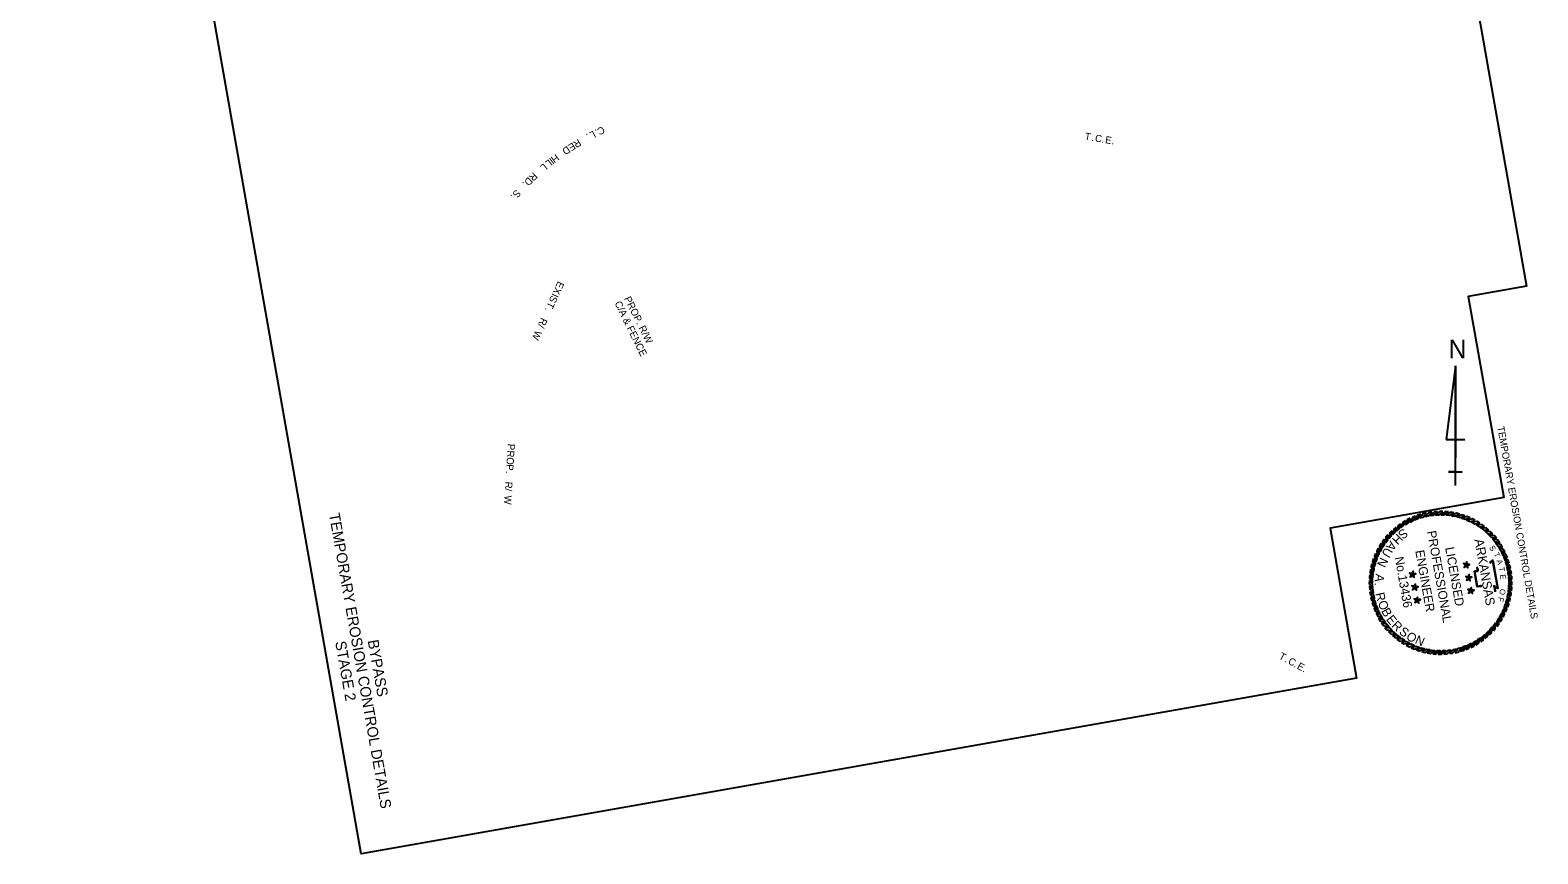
# Model space of a CAD drawing. Extents: x 979945 to 981206, y 1838799 to 1840551.
# Drawn here: x 979945 to 981206, y 1838799 to 1839488 of the extents above; entities that cross this region are included whole.
import ezdxf

# ---------------------------------------------------------------- set-up
doc = ezdxf.new("R2010")
doc.units = 0
for name, color, linetype in [('1', 7, 'Continuous'), ('60', 7, 'Continuous'), ('63', 7, 'Continuous'), ('Default', 7, 'Continuous'), ('G-ANNO-SYMB', 7, 'Continuous'), ('R_Draft', 7, 'Continuous')]:
    doc.layers.add(name, color=color, linetype=linetype)

msp = doc.modelspace()

# ---------------------------------------------------------------- linework, layer by layer
at = {"layer": '63'}
for p, q in [((981136.7, 1839206.9), (981129, 1839145.3)), ((981136.7, 1839106.9), (981136.7, 1839206.9)), ((981136.7, 1839206.9), (981136.7, 1839129.9)), ((981129, 1839145.3), (981144.4, 1839145.3)), ((981136.7, 1839106.9), (981136.7, 1839129.9)), ((981136.7, 1839118.4), (981130.9, 1839118.4)), ((981130.9, 1839118.4), (981142.4, 1839118.4)), ((981136.7, 1839106.9), (981136.7, 1839118.4))]:
    msp.add_line(p, q, dxfattribs=at)
at = {"layer": 'Default'}
msp.add_lwpolyline([(979944.5, 1840369.9), (980971, 1840550.9), (981196.2, 1839273.6), (981147.4, 1839265), (981177.1, 1839096.8), (981031.8, 1839071.2), (981054, 1838945.6), (980221.5, 1838798.8)], close=True, dxfattribs=at)
msp.add_lwpolyline([(979944.5, 1840369.9), (980971, 1840550.9), (981196.2, 1839273.6), (981147.4, 1839265), (981177.1, 1839096.8), (981031.8, 1839071.2), (981054, 1838945.6), (980221.5, 1838798.8)], close=True, dxfattribs=at)
at = {"layer": 'G-ANNO-SYMB'}
for points in [[(981094.8, 1839077.3), (981092.6, 1839076), (981091, 1839071.7), (981093.3, 1839073.3)], [(981098.9, 1839079.5), (981096.6, 1839078.3), (981094.8, 1839074.2), (981097.2, 1839075.5)], [(981103.3, 1839081.3), (981100.9, 1839080.3), (981098.7, 1839076.3), (981101.2, 1839077.5)], [(981107.7, 1839082.8), (981105.2, 1839082), (981102.8, 1839078.2), (981105.3, 1839079.2)], [(981112.2, 1839083.9), (981109.7, 1839083.3), (981107, 1839079.7), (981109.6, 1839080.5)], [(981116.9, 1839084.7), (981114.3, 1839084.3), (981111.3, 1839080.9), (981114, 1839081.5)], [(981121.5, 1839085.1), (981119, 1839084.9), (981115.7, 1839081.7), (981118.4, 1839082.1)], [(981126.2, 1839085.1), (981123.7, 1839085.1), (981120.1, 1839082.2), (981122.9, 1839082.4)], [(981130.9, 1839084.8), (981128.3, 1839085), (981124.6, 1839082.4), (981127.3, 1839082.3)], [(981135.5, 1839084.1), (981133, 1839084.5), (981129, 1839082.2), (981131.8, 1839081.9)], [(981140.1, 1839083), (981137.6, 1839083.6), (981133.5, 1839081.6), (981136.2, 1839081.1)], [(981144.5, 1839081.6), (981142.1, 1839082.4), (981137.8, 1839080.8), (981140.5, 1839080)], [(981148.9, 1839079.8), (981146.5, 1839080.8), (981142.1, 1839079.5), (981144.8, 1839078.6)], [(981153.1, 1839077.7), (981150.8, 1839078.9), (981146.3, 1839077.9), (981148.9, 1839076.8)], [(981080.2, 1839065.7), (981078.5, 1839063.7), (981078.4, 1839059.2), (981080.1, 1839061.3)], [(981083.5, 1839069), (981081.7, 1839067.2), (981081.2, 1839062.7), (981083, 1839064.7)], [(981087, 1839072.1), (981085.1, 1839070.4), (981084.2, 1839065.9), (981086.2, 1839067.8)], [(981090.8, 1839074.8), (981088.7, 1839073.4), (981087.5, 1839068.9), (981089.7, 1839070.7)], [(981157.1, 1839075.3), (981154.9, 1839076.7), (981150.4, 1839076.1), (981152.8, 1839074.7)], [(981160.9, 1839072.6), (981158.8, 1839074.1), (981154.3, 1839073.9), (981156.6, 1839072.3)], [(981164.5, 1839069.5), (981162.5, 1839071.2), (981158, 1839071.4), (981160.2, 1839069.7)], [(981167.8, 1839066.3), (981166, 1839068.1), (981161.5, 1839068.6), (981163.5, 1839066.7)], [(981170.9, 1839062.7), (981169.2, 1839064.7), (981164.7, 1839065.5), (981166.6, 1839063.5)], [(981072, 1839054.3), (981070.8, 1839052), (981071.8, 1839047.5), (981072.9, 1839050)], [(981074.5, 1839058.3), (981073.1, 1839056.1), (981073.7, 1839051.6), (981075, 1839054)], [(981077.2, 1839062.1), (981075.6, 1839060), (981075.9, 1839055.5), (981077.4, 1839057.8)], [(981173.7, 1839058.9), (981172.2, 1839061), (981167.8, 1839062.2), (981169.5, 1839060.1)], [(981176.1, 1839055), (981174.8, 1839057.2), (981170.5, 1839058.7), (981172.1, 1839056.4)], [(981178.3, 1839050.8), (981177.1, 1839053.1), (981173, 1839055), (981174.3, 1839052.6)], [(981066.8, 1839041.3), (981066.1, 1839038.8), (981068.1, 1839034.7), (981068.6, 1839037.4)], [(981068.2, 1839045.7), (981067.3, 1839043.3), (981069, 1839039), (981069.7, 1839041.7)], [(981069.9, 1839050.1), (981068.9, 1839047.7), (981070.2, 1839043.3), (981071.2, 1839045.9)], [(981145.8, 1839040.3), (981145.3, 1839041.2), (981143.3, 1839041.5), (981144.8, 1839040.1)], [(981145.8, 1839040.3), (981144.8, 1839040.1), (981143.9, 1839038.4), (981145.6, 1839039.3)], [(981145.8, 1839040.3), (981146.5, 1839041.1), (981146.2, 1839043), (981145.3, 1839041.2)], [(981145.8, 1839040.3), (981145.6, 1839039.3), (981147.1, 1839037.9), (981146.7, 1839039.9)], [(981145.8, 1839040.3), (981146.7, 1839039.9), (981148.5, 1839040.8), (981146.5, 1839041.1)], [(981180.1, 1839046.5), (981179.2, 1839048.9), (981175.1, 1839051.1), (981176.3, 1839048.5)], [(981181.6, 1839042), (981180.8, 1839044.5), (981177, 1839047), (981178, 1839044.4)], [(981182.7, 1839037.5), (981182.1, 1839040), (981178.5, 1839042.8), (981179.3, 1839040.1)], [(981064.7, 1839027.4), (981064.6, 1839024.8), (981067.5, 1839021.3), (981067.4, 1839024)], [(981065, 1839032.1), (981064.8, 1839029.5), (981067.3, 1839025.7), (981067.4, 1839028.5)], [(981065.7, 1839036.7), (981065.3, 1839034.2), (981067.5, 1839030.2), (981067.8, 1839033)], [(981100.8, 1839032.4), (981100.3, 1839033.3), (981098.3, 1839033.6), (981099.8, 1839032.2)], [(981100.8, 1839032.4), (981099.8, 1839032.2), (981098.9, 1839030.4), (981100.6, 1839031.4)], [(981100.8, 1839032.4), (981101.5, 1839033.1), (981101.2, 1839035.1), (981100.3, 1839033.3)], [(981100.8, 1839032.4), (981100.6, 1839031.4), (981102.1, 1839030), (981101.7, 1839031.9)], [(981100.8, 1839032.4), (981101.7, 1839031.9), (981103.5, 1839032.9), (981101.5, 1839033.1)], [(981147.7, 1839029.6), (981147.2, 1839030.5), (981145.2, 1839030.8), (981146.6, 1839029.4)], [(981147.7, 1839029.6), (981146.6, 1839029.4), (981145.8, 1839027.6), (981147.5, 1839028.6)], [(981147.7, 1839029.6), (981148.4, 1839030.3), (981148.1, 1839032.3), (981147.2, 1839030.5)], [(981147.7, 1839029.6), (981147.5, 1839028.6), (981149, 1839027.2), (981148.6, 1839029.1)], [(981147.7, 1839029.6), (981148.6, 1839029.1), (981150.4, 1839030.1), (981148.4, 1839030.3)], [(981183.5, 1839032.9), (981183.1, 1839035.4), (981179.7, 1839038.5), (981180.3, 1839035.8)], [(981183.9, 1839028.2), (981183.7, 1839030.8), (981180.6, 1839034.1), (981180.9, 1839031.3)], [(981183.9, 1839023.5), (981183.9, 1839026.1), (981181.1, 1839029.6), (981181.2, 1839026.9)], [(981064.7, 1839022.7), (981064.9, 1839020.2), (981068, 1839016.8), (981067.7, 1839019.6)], [(981065.1, 1839018), (981065.5, 1839015.5), (981068.9, 1839012.4), (981068.3, 1839015.2)], [(981102.7, 1839021.7), (981102.2, 1839022.6), (981100.2, 1839022.8), (981101.7, 1839021.5)], [(981102.7, 1839021.7), (981101.7, 1839021.5), (981100.8, 1839019.7), (981102.5, 1839020.6)], [(981102.7, 1839021.7), (981103.4, 1839022.4), (981103.1, 1839024.4), (981102.2, 1839022.6)], [(981102.7, 1839021.7), (981102.5, 1839020.6), (981104, 1839019.2), (981103.6, 1839021.2)], [(981102.7, 1839021.7), (981103.6, 1839021.2), (981105.4, 1839022.1), (981103.4, 1839022.4)], [(981149.6, 1839018.8), (981149.1, 1839019.8), (981147.1, 1839020), (981148.5, 1839018.7)], [(981149.6, 1839018.8), (981148.5, 1839018.7), (981147.7, 1839016.9), (981149.4, 1839017.8)], [(981149.6, 1839018.8), (981150.3, 1839019.6), (981149.9, 1839021.5), (981149.1, 1839019.8)], [(981149.6, 1839018.8), (981149.4, 1839017.8), (981150.8, 1839016.4), (981150.5, 1839018.4)], [(981149.6, 1839018.8), (981150.5, 1839018.4), (981152.3, 1839019.3), (981150.3, 1839019.6)], [(981181.8, 1839009.7), (981182.4, 1839012.1), (981180.5, 1839016.3), (981180, 1839013.5)], [(981182.9, 1839014.2), (981183.3, 1839016.7), (981181, 1839020.7), (981180.7, 1839018)], [(981183.6, 1839018.8), (981183.8, 1839021.4), (981181.2, 1839025.2), (981181.1, 1839022.4)], [(981065.8, 1839013.4), (981066.4, 1839010.9), (981070, 1839008.1), (981069.3, 1839010.8)], [(981067, 1839008.9), (981067.7, 1839006.4), (981071.6, 1839003.9), (981070.6, 1839006.5)], [(981068.4, 1839004.4), (981069.4, 1839002.1), (981073.4, 1838999.9), (981072.2, 1839002.4)], [(981104.6, 1839010.9), (981104.1, 1839011.8), (981102.1, 1839012.1), (981103.6, 1839010.7)], [(981104.6, 1839010.9), (981103.6, 1839010.7), (981102.7, 1839008.9), (981104.4, 1839009.9)], [(981104.6, 1839010.9), (981105.3, 1839011.7), (981105, 1839013.6), (981104.1, 1839011.8)], [(981104.6, 1839010.9), (981104.4, 1839009.9), (981105.9, 1839008.5), (981105.5, 1839010.5)], [(981104.6, 1839010.9), (981105.5, 1839010.5), (981107.3, 1839011.4), (981105.3, 1839011.7)], [(981176.5, 1838996.7), (981177.7, 1838998.9), (981176.8, 1839003.4), (981175.6, 1839000.9)], [(981178.6, 1839000.9), (981179.6, 1839003.2), (981178.3, 1839007.6), (981177.4, 1839005)], [(981180.4, 1839005.2), (981181.2, 1839007.6), (981179.6, 1839011.9), (981178.8, 1839009.2)], [(981070.3, 1839000.1), (981071.4, 1838997.8), (981075.6, 1838996), (981074.2, 1838998.4)], [(981072.4, 1838996), (981073.7, 1838993.8), (981078.1, 1838992.2), (981076.5, 1838994.5)], [(981074.9, 1838992), (981076.4, 1838989.9), (981080.8, 1838988.7), (981079.1, 1838990.9)], [(981168.4, 1838985.3), (981170, 1838987.2), (981170.2, 1838991.8), (981168.5, 1838989.6)], [(981171.4, 1838988.8), (981172.9, 1838990.9), (981172.7, 1838995.5), (981171.2, 1838993.1)], [(981174.1, 1838992.7), (981175.5, 1838994.8), (981174.9, 1838999.4), (981173.5, 1838996.9)], [(981077.7, 1838988.2), (981079.3, 1838986.2), (981083.8, 1838985.4), (981081.9, 1838987.4)], [(981080.7, 1838984.7), (981082.5, 1838982.8), (981087.1, 1838982.4), (981085, 1838984.2)], [(981084.1, 1838981.4), (981086, 1838979.7), (981090.6, 1838979.6), (981088.4, 1838981.3)], [(981087.7, 1838978.4), (981089.7, 1838976.8), (981094.3, 1838977.1), (981092, 1838978.6)], [(981091.5, 1838975.6), (981093.6, 1838974.3), (981098.2, 1838974.9), (981095.7, 1838976.2)], [(981149.6, 1838971.5), (981151.9, 1838972.6), (981153.8, 1838976.8), (981151.4, 1838975.4)], [(981153.8, 1838973.6), (981156, 1838974.9), (981157.5, 1838979.2), (981155.2, 1838977.7)], [(981157.8, 1838976.1), (981159.9, 1838977.6), (981161, 1838982), (981158.9, 1838980.2)], [(981161.5, 1838978.9), (981163.5, 1838980.5), (981164.3, 1838985), (981162.3, 1838983.1)], [(981165.1, 1838981.9), (981166.9, 1838983.7), (981167.4, 1838988.3), (981165.5, 1838986.2)], [(981095.5, 1838973.2), (981097.8, 1838972), (981102.2, 1838973), (981099.7, 1838974.1)], [(981099.7, 1838971.1), (981102, 1838970.1), (981106.4, 1838971.4), (981103.8, 1838972.3)], [(981104, 1838969.4), (981106.4, 1838968.5), (981110.7, 1838970.2), (981108, 1838970.9)], [(981108.5, 1838967.9), (981111, 1838967.3), (981115.1, 1838969.3), (981112.4, 1838969.8)], [(981113, 1838966.9), (981115.6, 1838966.4), (981119.5, 1838968.7), (981116.8, 1838969)], [(981117.7, 1838966.2), (981120.2, 1838965.9), (981124, 1838968.5), (981121.2, 1838968.6)], [(981122.3, 1838965.8), (981124.9, 1838965.8), (981128.5, 1838968.7), (981125.7, 1838968.5)], [(981127, 1838965.9), (981129.6, 1838966), (981132.9, 1838969.2), (981130.2, 1838968.8)], [(981131.7, 1838966.3), (981134.2, 1838966.6), (981137.3, 1838970), (981134.6, 1838969.5)], [(981136.3, 1838967), (981138.8, 1838967.6), (981141.6, 1838971.2), (981138.9, 1838970.4)], [(981140.9, 1838968.2), (981143.3, 1838968.9), (981145.8, 1838972.8), (981143.2, 1838971.8)], [(981145.3, 1838969.6), (981147.7, 1838970.6), (981149.9, 1838974.6), (981147.4, 1838973.4)]]:
    msp.add_lwpolyline(points, close=True, dxfattribs=at)
for points in [[(981165.3, 1839042.4), (981168, 1839044.3), (981172.2, 1839020.6), (981169.3, 1839022.1), (981169.6, 1839020.5), (981169.9, 1839019.2), (981170, 1839017.8)], [(981165.5, 1839042.1), (981167.7, 1839043.6), (981171.7, 1839021.3), (981168.8, 1839022.8), (981169.3, 1839020.5), (981169.5, 1839019.1), (981169.6, 1839017.8)], [(981158.6, 1839022), (981158.2, 1839022.4), (981157.7, 1839022.4), (981156.4, 1839022.4), (981154.8, 1839022.1), (981152.5, 1839035.3), (981154.7, 1839035.7), (981155.2, 1839035.8), (981155.2, 1839036.3), (981154.9, 1839038.2), (981155.4, 1839038.6)], [(981158.9, 1839022.3), (981158.4, 1839022.8), (981157.7, 1839022.8), (981156.4, 1839022.7), (981155.1, 1839022.5), (981152.9, 1839035), (981154.7, 1839035.3), (981155.5, 1839035.4), (981155.6, 1839036.4), (981155.3, 1839038.1), (981155.6, 1839038.4)]]:
    msp.add_lwpolyline(points, dxfattribs=at)

# ---------------------------------------------------------------- texts
at = {"layer": '1'}
msp.add_text('TEMPORARY EROSION CONTROL DETAILS', height=5.862, rotation=280, dxfattribs=at).set_placement((981171.6, 1839155.8))
at = {"layer": '60'}
for s, p in [('TEMPORARY EROSION CONTROL DETAILS', (980194.4, 1839083)), ('STAGE 2', (980199.6, 1838976)), ('BYPASS', (980226.8, 1838977.1))]:
    msp.add_text(s, height=9, rotation=280, dxfattribs=at).set_placement(p)
at = {"layer": '63'}
msp.add_text('N', height=15.4, rotation=0, dxfattribs=at).set_placement((981131, 1839213.3))
at = {"layer": 'G-ANNO-SYMB'}
for s, height, rotation, p in [('H', 7.5, 225.619, (981088, 1839067.1)), ('S', 7.5, 218.1636, (981093.2, 1839071.4)), ('PROFESSIONAL', 7.5, 280, (981112.9, 1839068.4)), ('U', 7.5, 240.9026, (981078.1, 1839055.7)), ('A', 7.5, 233.4472, (981082.1, 1839061.2)), ('ENGINEER', 7.5, 280, (981103, 1839052.2)), ('LICENSED', 7.5, 280, (981128, 1839054.8)), ('ARKANSAS', 7.75, 280, (981152.5, 1839061.5)), ('S', 4.75, 299.7726, (981164.6, 1839055)), ('N', 7.5, 244.9326, (981073.9, 1839047.3)), ('No.13436', 7.47, 280, (981085.8, 1839046.7)), ('T', 4.75, 296.9015, (981168.4, 1839049.5)), ('A', 4.75, 288.6788, (981170.8, 1839044.1)), ('A', 7.5, 263.0991, (981069.9, 1839033.3)), ('T', 4.75, 281.4789, (981172.8, 1839038.2)), ('E', 4.75, 276.672, (981173.7, 1839032.2)), ('.', 7.5, 271.3, (981069, 1839025.7)), ('R', 7.5, 283.2287, (981069.6, 1839016.5)), ('O', 4.75, 261.2218, (981174.1, 1839020.6)), ('O', 7.5, 291.4296, (981071.5, 1839009)), ('B', 7.5, 298.885, (981074.3, 1839001.9)), ('F', 4.75, 255.3628, (981172.8, 1839013.9)), ('E', 7.5, 307.8315, (981078.3, 1838994.9)), ('R', 7.5, 315.6597, (981082.7, 1838989.2)), ('S', 7.5, 323.4878, (981088.9, 1838983.3)), ('O', 7.5, 324.7757, (981094.7, 1838979.1)), ('N', 7.5, 336.1007, (981102.2, 1838975.1))]:
    msp.add_text(s, height=height, rotation=rotation, dxfattribs=at).set_placement(p)
at = {"layer": 'R_Draft'}
for s, rotation, p in [('C', 205.4365, (980423.3, 1839407.5)), ('E', 212.6769, (980398.2, 1839394)), ('R', 211.2408, (980403, 1839396.9)), ('.', 208.9789, (980410.8, 1839401.3)), ('L', 207.6146, (980415.6, 1839403.8)), ('.', 206.8726, (980418.2, 1839405.1)), ('T', 350.1918, (980826.2, 1839396.1)), ('.', 350.1918, (980831.9, 1839395.1)), ('C', 350.1918, (980834.8, 1839394.6)), ('.', 350.1918, (980840.4, 1839393.7)), ('E', 350.1918, (980843.3, 1839393.2)), ('.', 350.1918, (980848.6, 1839392.3)), ('I', 218.3616, (980379.8, 1839381.2)), ('H', 216.9973, (980384.1, 1839384.4)), ('D', 214.0412, (980393.7, 1839391.1)), ('R', 223.1127, (980365.4, 1839369.1)), ('L', 220.2285, (980374, 1839376.6)), ('L', 218.8642, (980378.2, 1839380)), ('.', 225.985, (980357.2, 1839361.3)), ('D', 224.5489, (980361.3, 1839365.2)), ('.', 229.683, (980347.3, 1839350.6)), ('S', 228.2469, (980351.1, 1839354.8)), ('I', 245.3622, (980381.3, 1839268)), ('X', 245.3622, (980383.7, 1839273.2)), ('E', 245.3622, (980386, 1839278.1)), ('.', 245.3622, (980375.7, 1839255.7)), ('T', 245.3622, (980378.1, 1839261)), ('S', 245.3622, (980380.5, 1839266.2)), ('C/A & FENCE', 296.2946, (980433.1, 1839259.3)), ('PROP. R/W', 296.2946, (980441.2, 1839263.2)), ('/', 245.3622, (980369.6, 1839242.4)), ('R', 245.3622, (980372, 1839247.6)), ('W', 245.3622, (980367.2, 1839237.1)), ('P', 266.507, (980344, 1839141.9)), ('O', 266.507, (980343.3, 1839130.6)), ('R', 266.507, (980343.6, 1839136.3)), ('.', 266.507, (980342.6, 1839119.1)), ('P', 266.507, (980342.9, 1839124.8)), ('/', 266.507, (980341.7, 1839104.5)), ('R', 266.507, (980342, 1839110.2)), ('W', 266.507, (980341.3, 1839098.7)), ('T', 330.9256, (980988.4, 1838962.4)), ('.', 330.9256, (980993.5, 1838959.6)), ('C', 330.9256, (980996.1, 1838958.2)), ('.', 330.9256, (981001, 1838955.4)), ('E', 330.9256, (981003.6, 1838954)), ('.', 330.9256, (981008.3, 1838951.4))]:
    msp.add_text(s, height=6, rotation=rotation, dxfattribs=at).set_placement(p)

doc.saveas('drawing.dxf')
